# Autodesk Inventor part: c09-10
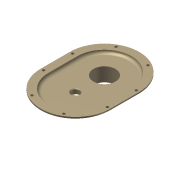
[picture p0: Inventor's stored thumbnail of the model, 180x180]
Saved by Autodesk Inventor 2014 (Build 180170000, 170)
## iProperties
Created: 2010-12
Part Number: c09-10
Material: Generic
Document SubType Name: Modeling
Designer: Thom Tremblay
Density: 1 g/cm^3
Appearance: Wheat
Author: Thom Tremblay
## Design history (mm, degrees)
derived "c09-09.ipt"
hole "Hole1" diameter "d3" = 14; stored, may be unused: countersink angle "d7" = 90 deg, drill point angle "d9" = 118 deg; dims "d1" = 10, "d2" = 10, "d4" = 6, "d5" = 4, "d6" = 2, "d8" = 8
workplane "Work Plane1"
split "Split1"
workplane "Work Plane2"
split "Split2"
hole "Hole2" diameter "d14" = 3.242; stored, may be unused: countersink angle "d18" = 90 deg, drill point angle "d20" = 118 deg; dims "d12" = 10, "d13" = 10, "d15" = 8, "d16" = 4, "d17" = 2, "d19" = 10
pattern_circular "Circular Pattern1" dims angle "d22" = 360 deg
hole "Hole3" diameter "d26" = 38; stored, may be unused: countersink angle "d30" = 90 deg, drill point angle "d32" = 118 deg; dims "d27" = 8, "d28" = 4, "d29" = 2, "d31" = 10, "d45" = 10, "d46" = 10
sketch "Sketch2"
  geometry: L1 (-59.93, 0)-(-59.93, 50) reference; L2 (59.93, 50)-(59.93, 0) reference; L3 (-55, 50)-(-55, 0); L4 (55, 0)-(55, 50); A1 r 59.93 centre (0, 0) between (-59.93, 0) and (59.93, 0) reference; A2 r 59.93 centre (0, 50) between (59.93, 50) and (-59.93, 50) reference; A3 r 55 centre (0, 0) between (-55, 0) and (55, 0); A4 r 55 centre (0, 50) between (55, 50) and (-55, 50); 8 further points
  constraints: 8 point on circle, 4 coincident, 4 end point, 2 centre point, 2 horizontal alignment, 2 vertical alignment, 3 other
  dimensions: "d33" = 55 radius of A4; "d34" = 55 distance of point (27.5, 97.631) point (-27.5, 97.631)
hole "Hole4" sketch "Sketch2" at (-55, 0), (55, 0), (55, 50), (-55, 50), (-27.5, 97.631), (27.5, 97.631), (27.5, -47.631), (-27.5, -47.631) diameter "d35" = 4.5; stored, may be unused: countersink angle "d39" = 90 deg, drill point angle "d41" = 118 deg; dims "d36" = 8, "d37" = 4, "d38" = 90, "d40" = 10
chamfer "Chamfer1" distance "d42" = 1; stored, may be unused: second distance "d43" = 2, angle "d44" = 45 deg
feature "Solid1::Front cast.ipt" dims "d0" = 10
tag "TaggingFeature1"
body "Solid1"
other parameters: "d10" = -3, "d11" = -29
